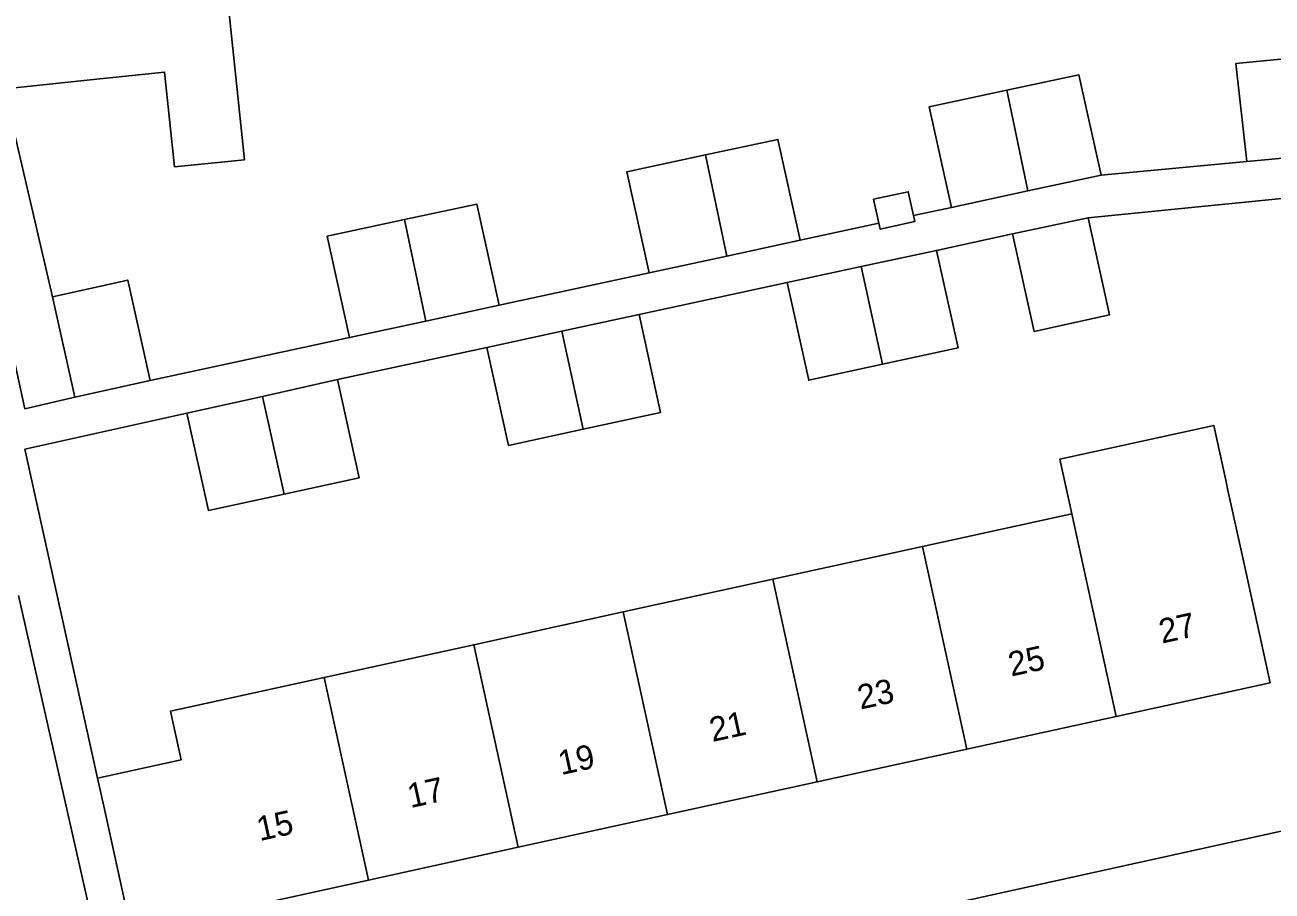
# Model space of a CAD drawing. Extents: x 160554 to 161248, y 385329 to 386506.
# Drawn here: x 160785.6 to 160836.9, y 385933.1 to 385968.7 of the extents above; entities that cross this region are included whole.
import ezdxf

# ---------------------------------------------------------------- set-up
doc = ezdxf.new("R2010")
doc.units = 0
for name, color, linetype in [('IMGEO_Erf', 7, 'Continuous'), ('IMGEO_Pand', 7, 'Continuous'), ('IMGEO_Pand_nummerreeks', 7, 'Continuous'), ('IMGEO_Voetpad_open', 7, 'Continuous')]:
    doc.layers.add(name, color=color, linetype=linetype)

msp = doc.modelspace()

# ---------------------------------------------------------------- linework, layer by layer
at = {"layer": 'IMGEO_Erf'}
for points in [[(160825.299, 385972.698), (160819.03, 385972.041), (160812.762, 385971.384), (160806.493, 385970.726), (160800.225, 385970.069), (160793.956, 385969.412), (160794.61, 385963.139), (160791.735, 385962.839), (160791.328, 385966.744), (160788.26, 385966.424), (160785.028, 385966.087)], [(160784.908, 385965.292), (160786.712, 385957.498), (160789.813, 385958.185), (160790.728, 385954.049), (160798.938, 385955.823), (160798.016, 385959.992), (160801.192, 385960.674), (160804.17, 385961.314), (160805.09, 385957.153), (160811.265, 385958.486), (160810.346, 385962.641), (160813.582, 385963.336), (160816.558, 385963.975), (160817.475, 385959.829), (160820.71, 385960.528), (160820.497, 385961.514), (160821.921, 385961.822), (160822.134, 385960.836), (160823.7, 385961.174), (160822.784, 385965.311), (160825.973, 385965.997), (160828.938, 385966.634), (160829.852, 385962.504), (160835.849, 385963.06), (160835.398, 385967.092), (160838.526, 385967.397)], [(160851.843, 385963.002), (160829.319, 385960.753), (160830.204, 385956.751), (160827.099, 385956.077), (160826.213, 385960.084), (160823.088, 385959.409), (160823.975, 385955.399), (160820.862, 385954.723), (160817.826, 385954.064), (160816.938, 385958.082), (160810.845, 385956.767), (160811.735, 385952.742), (160808.552, 385952.052), (160805.482, 385951.386), (160804.59, 385955.418), (160798.436, 385954.09), (160799.33, 385950.051), (160796.243, 385949.381), (160793.127, 385948.704), (160792.242, 385952.708), (160785.583, 385951.229), (160788.572, 385937.702), (160792.011, 385938.455), (160791.573, 385940.458), (160797.894, 385941.841), (160804.046, 385943.188), (160810.198, 385944.535), (160816.351, 385945.881), (160822.503, 385947.228), (160828.655, 385948.574), (160828.162, 385950.825), (160834.488, 385952.21), (160834.981, 385949.959), (160835.061, 385949.595), (160835.736, 385946.509), (160836.805, 385941.624), (160830.48, 385940.24), (160824.328, 385938.893), (160818.176, 385937.546), (160812.023, 385936.199), (160805.871, 385934.853), (160799.719, 385933.506), (160793.395, 385932.122)], [(160739.836, 385914.053), (160789.869, 385925.075), (160785.322, 385945.206)], [(160791.225, 385925.374), (160838.197, 385935.721)]]:
    msp.add_lwpolyline(points, dxfattribs=at)
at = {"layer": 'IMGEO_Pand'}
for points in [[(160784.017, 385975.764), (160785.028, 385966.087), (160788.26, 385966.424), (160791.328, 385966.744), (160791.735, 385962.839), (160794.61, 385963.139), (160793.956, 385969.412), (160793.068, 385977.926), (160786.905, 385977.282), (160787.031, 385976.079), (160786.712, 385976.046), (160786.746, 385975.727), (160784.369, 385975.479), (160784.335, 385975.797)], [(160838.948, 385963.347), (160838.526, 385967.397), (160835.398, 385967.092), (160835.849, 385963.06)], [(160829.852, 385962.504), (160828.938, 385966.634), (160825.973, 385965.997), (160826.844, 385961.854)], [(160826.844, 385961.854), (160825.973, 385965.997), (160822.784, 385965.311), (160823.7, 385961.174)], [(160817.475, 385959.829), (160816.558, 385963.975), (160813.582, 385963.336), (160814.457, 385959.176)], [(160814.457, 385959.176), (160813.582, 385963.336), (160810.346, 385962.641), (160811.265, 385958.486)], [(160820.497, 385961.514), (160820.71, 385960.528), (160820.763, 385960.284), (160822.187, 385960.592), (160822.134, 385960.836), (160821.921, 385961.822)], [(160805.09, 385957.153), (160804.17, 385961.314), (160801.192, 385960.674), (160802.07, 385956.5)], [(160802.07, 385956.5), (160801.192, 385960.674), (160798.016, 385959.992), (160798.938, 385955.823)], [(160826.213, 385960.084), (160827.099, 385956.077), (160830.204, 385956.751), (160829.319, 385960.753)], [(160819.982, 385958.739), (160820.862, 385954.723), (160823.975, 385955.399), (160823.088, 385959.409)], [(160816.938, 385958.082), (160817.826, 385954.064), (160820.862, 385954.723), (160819.982, 385958.739)], [(160789.813, 385958.185), (160786.712, 385957.498), (160787.628, 385953.363), (160790.728, 385954.049)], [(160807.669, 385956.082), (160808.552, 385952.052), (160811.735, 385952.742), (160810.845, 385956.767)], [(160804.59, 385955.418), (160805.482, 385951.386), (160808.552, 385952.052), (160807.669, 385956.082)], [(160795.362, 385953.404), (160796.243, 385949.381), (160799.33, 385950.051), (160798.436, 385954.09)], [(160792.242, 385952.708), (160793.127, 385948.704), (160796.243, 385949.381), (160795.362, 385953.404)], [(160828.655, 385948.574), (160830.48, 385940.24), (160836.805, 385941.624), (160835.736, 385946.509), (160835.061, 385949.595), (160834.981, 385949.959), (160834.488, 385952.21), (160828.162, 385950.825)], [(160828.655, 385948.574), (160822.503, 385947.228), (160824.328, 385938.893), (160830.48, 385940.24)], [(160818.176, 385937.546), (160824.328, 385938.893), (160822.503, 385947.228), (160816.351, 385945.881)], [(160816.351, 385945.881), (160810.198, 385944.535), (160812.023, 385936.199), (160818.176, 385937.546)], [(160805.871, 385934.853), (160812.023, 385936.199), (160810.198, 385944.535), (160804.046, 385943.188)], [(160804.046, 385943.188), (160797.894, 385941.841), (160799.719, 385933.506), (160805.871, 385934.853)], [(160789.893, 385931.664), (160793.331, 385932.416), (160793.395, 385932.122), (160799.719, 385933.506), (160797.894, 385941.841), (160791.573, 385940.458), (160792.011, 385938.455), (160788.572, 385937.702), (160788.824, 385936.549)]]:
    msp.add_lwpolyline(points, close=True, dxfattribs=at)
at = {"layer": 'IMGEO_Voetpad_open'}
for points in [[(160783.292, 385962.191), (160784.098, 385958.652), (160784.303, 385958.697), (160785.581, 385952.894), (160787.628, 385953.363), (160786.712, 385957.498), (160784.908, 385965.292), (160784.892, 385965.363), (160783.331, 385979.37)], [(160838.948, 385963.347), (160835.849, 385963.06), (160829.852, 385962.504), (160826.844, 385961.854), (160823.7, 385961.174), (160822.134, 385960.836), (160822.187, 385960.592), (160820.763, 385960.284), (160820.71, 385960.528), (160817.475, 385959.829), (160814.457, 385959.176), (160811.265, 385958.486), (160805.09, 385957.153), (160802.07, 385956.5), (160798.938, 385955.823), (160790.728, 385954.049), (160787.628, 385953.363), (160785.581, 385952.894)], [(160785.322, 385945.206), (160789.869, 385925.075), (160791.225, 385925.374), (160789.893, 385931.664), (160788.824, 385936.549), (160788.572, 385937.702), (160785.583, 385951.229), (160792.242, 385952.708), (160795.362, 385953.404), (160798.436, 385954.09), (160804.59, 385955.418), (160807.669, 385956.082), (160810.845, 385956.767), (160816.938, 385958.082), (160819.982, 385958.739), (160823.088, 385959.409), (160826.213, 385960.084), (160829.319, 385960.753), (160851.843, 385963.002)], [(160841.431, 385936.281), (160838.197, 385935.721), (160791.225, 385925.374), (160789.869, 385925.075), (160739.836, 385914.053)]]:
    msp.add_lwpolyline(points, dxfattribs=at)

# ---------------------------------------------------------------- texts
at = {"layer": 'IMGEO_Pand_nummerreeks'}
for s, rotation, p in [('27', 12.3472, (160832.358, 385943.23)), ('25', 12.3467, (160826.157, 385941.874)), ('23', 12.3467, (160819.955, 385940.516)), ('21', 12.3467, (160813.865, 385939.183)), ('19', 12.3467, (160807.641, 385937.82)), ('17', 12.3467, (160801.44, 385936.463)), ('15', 12.3467, (160795.239, 385935.106))]:
    msp.add_text(s, height=1, rotation=rotation, dxfattribs=at).set_placement(p)

doc.saveas('drawing.dxf')
